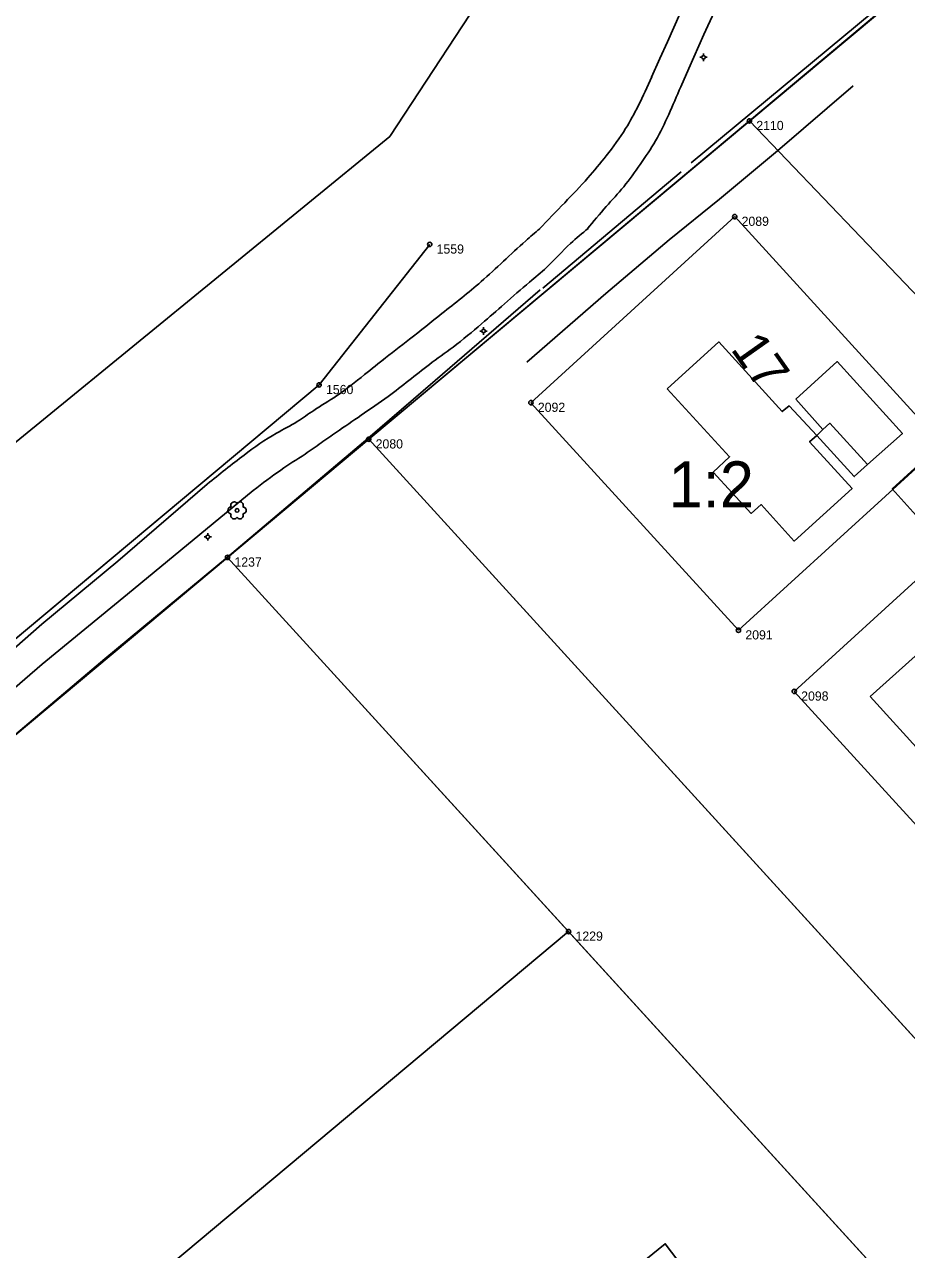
# Model space of a CAD drawing. Extents: x 1517478 to 1518189, y 6494860 to 6495389.
# Drawn here: x 1517883.6 to 1517979.5, y 6495107.4 to 6495240.6 of the extents above; entities that cross this region are included whole.
import ezdxf

# ---------------------------------------------------------------- set-up
doc = ezdxf.new("R2010")
doc.units = 0
for name, color, linetype in [('adress', 7, 'Continuous'), ('bostadshus', 7, 'Continuous'), ('fastighetsbeteckning', 7, 'Continuous'), ('gc_vag', 7, 'Continuous'), ('grans', 7, 'Continuous'), ('granspunkt', 7, 'Continuous'), ('granspunkt_text', 7, 'Continuous'), ('hack', 7, 'Continuous'), ('kvartersgrans', 7, 'Continuous'), ('kvartersgrans_utan_fastgr', 7, 'Continuous'), ('kvartersytor', 7, 'Continuous'), ('ledningar', 7, 'Continuous'), ('lovtrad', 7, 'Continuous'), ('parkeringskant', 7, 'Continuous'), ('skarmtak', 7, 'Continuous'), ('staket', 7, 'Continuous'), ('stolpe_belysning', 7, 'Continuous'), ('uthus', 7, 'Continuous')]:
    doc.layers.add(name, color=color, linetype=linetype)

msp = doc.modelspace()

# ---------------------------------------------------------------- linework, layer by layer
at = {"layer": 'bostadshus'}
for points in [[(1517953.5, 6495201.02), (1517959.1, 6495206.11), (1517966.02, 6495198.53), (1517966.76, 6495199.15), (1517969.76, 6495195.93), (1517968.99, 6495195.25), (1517973.6, 6495190.18), (1517967.31, 6495184.46), (1517963.71, 6495188.43), (1517962.62, 6495187.46), (1517958.49, 6495191.93), (1517960.28, 6495193.62), (1517953.5, 6495201.02)], [(1517975.57, 6495167.55), (1517980.48, 6495171.93), (1517981.83, 6495170.45), (1517987.06, 6495175.28), (1517988.1, 6495174.14), (1517992.61, 6495178.29), (1517991.59, 6495179.38), (1517991.82, 6495179.58), (1517997.11, 6495173.74), (1517992.09, 6495169.26), (1517991.75, 6495169.62), (1517988.32, 6495166.48), (1517991.2, 6495163.3), (1517987.55, 6495160.07), (1517984.13, 6495163.84), (1517981.3, 6495161.27), (1517975.57, 6495167.55)]]:
    msp.add_lwpolyline(points, dxfattribs=at)
at = {"layer": 'gc_vag'}
for points in [[(1517960.6, 6495254.37), (1517959.63, 6495252.05), (1517958.37, 6495249.52), (1517956.69, 6495245.83), (1517954.9, 6495241.83), (1517953.53, 6495238.72), (1517952.69, 6495236.93), (1517951.8, 6495234.88)], [(1517966.27, 6495254.47), (1517962.16, 6495249.73), (1517959.53, 6495243.94), (1517957.48, 6495239.51), (1517955.85, 6495235.83), (1517954.98, 6495233.83)], [(1517988.68, 6495187.89), (1517988.86, 6495187.55), (1517984.15, 6495183.26), (1517977.97, 6495190.13), (1517982.05, 6495193.87)], [(1517877.91, 6495168.79), (1517885.48, 6495175.44), (1517893.74, 6495182.28), (1517903.48, 6495190.65)], [(1517877.95, 6495164.55), (1517885.53, 6495171.07), (1517894.79, 6495178.7), (1517908.48, 6495189.97)]]:
    msp.add_lwpolyline(points, dxfattribs=at)
for points in [[(1517939.59, 6495218.37), (1517942.35, 6495221.24), (1517944.87, 6495223.93), (1517946.87, 6495226.35), (1517948.98, 6495229.3), (1517950.35, 6495231.77), (1517951.82, 6495234.93)], [(1517944.8, 6495218.37), (1517946.87, 6495220.82), (1517948.77, 6495222.98), (1517950.56, 6495225.4), (1517952.24, 6495227.98), (1517953.66, 6495230.83), (1517954.98, 6495233.83)], [(1517908.48, 6495189.97), (1517911.48, 6495192.18), (1517914.11, 6495193.92), (1517915.85, 6495195.13), (1517917.53, 6495196.29), (1517920.21, 6495198.13), (1517923.16, 6495200.18), (1517927.63, 6495203.66), (1517930.21, 6495205.55), (1517933.32, 6495208.08), (1517935.79, 6495210.24), (1517938.53, 6495212.61), (1517940.37, 6495214.19), (1517943, 6495216.82), (1517944.9, 6495218.45)], [(1517922.49, 6495204.07), (1517925.48, 6495206.4), (1517929, 6495209.19), (1517933.26, 6495212.66), (1517938.11, 6495217.09), (1517939.63, 6495218.4)], [(1517903.48, 6495190.65), (1517907.48, 6495193.81), (1517911, 6495196.18), (1517913.27, 6495197.45), (1517915.06, 6495198.66), (1517917.53, 6495200.24), (1517920.58, 6495202.55), (1517922.9, 6495204.4)]]:
    msp.add_spline(points, degree=3, dxfattribs=at)
at = {"layer": 'grans'}
for p, q in [((1517976.27, 6495241.68), (1517962.44, 6495230.13)), ((1517962.44, 6495230.13), (1517921.04, 6495195.52)), ((1517962.44, 6495230.13), (1517990.19, 6495201.16)), ((1517938.68, 6495199.5), (1517960.84, 6495219.72)), ((1517960.84, 6495219.72), (1517983.41, 6495194.98)), ((1517915.64, 6495201.43), (1517927.67, 6495216.7)), ((1517827.1, 6495127.44), (1517915.64, 6495201.43)), ((1517961.25, 6495174.76), (1517938.68, 6495199.5)), ((1517921.04, 6495195.52), (1517905.68, 6495182.68)), ((1517983.41, 6495194.98), (1517961.25, 6495174.76)), ((1517967.32, 6495168.11), (1517989.48, 6495188.33)), ((1517905.68, 6495182.68), (1517832.22, 6495121.28)), ((1517905.68, 6495182.68), (1517942.78, 6495142.01)), ((1517992.59, 6495140.41), (1517967.32, 6495168.11)), ((1517942.78, 6495142.01), (1517887.66, 6495095.94)), ((1517942.78, 6495142.01), (1518054.69, 6495019.3))]:
    msp.add_line(p, q, dxfattribs=at)
at = {"layer": 'granspunkt'}
for centre in [(1517962.44, 6495230.13), (1517960.84, 6495219.72), (1517927.67, 6495216.7), (1517915.64, 6495201.43), (1517938.68, 6495199.5), (1517921.04, 6495195.52), (1517905.68, 6495182.68), (1517961.25, 6495174.76), (1517967.32, 6495168.11), (1517942.78, 6495142.01)]:
    msp.add_circle(centre, 0.237, dxfattribs=at)
at = {"layer": 'hack'}
msp.add_line((1517928.27, 6495201.92), (1517939.69, 6495211.77), dxfattribs=at)
for points in [[(1517973.71, 6495233.93), (1517965.5, 6495226.88), (1517959.19, 6495221.61), (1517953.72, 6495217.19), (1517946.82, 6495211.35), (1517938.22, 6495203.92)], [(1517905.67, 6495182.7), (1517920.95, 6495195.6), (1517928.27, 6495201.92)], [(1517879.54, 6495160.85), (1517892.35, 6495171.65), (1517905.67, 6495182.7)]]:
    msp.add_lwpolyline(points, dxfattribs=at)
at = {"layer": 'kvartersgrans'}
for p, q in [((1517962.44, 6495230.13), (1517921.04, 6495195.52)), ((1517915.64, 6495201.43), (1517927.67, 6495216.7))]:
    msp.add_line(p, q, dxfattribs=at)
for points in [[(1517962.44, 6495230.13), (1517976.27, 6495241.68), (1517987.04, 6495250.68)], [(1517915.64, 6495201.43), (1517827.1, 6495127.44), (1517815.51, 6495117.75), (1517760.41, 6495089.02)], [(1517905.68, 6495182.68), (1517832.22, 6495121.28), (1517819.97, 6495111.05)], [(1517905.68, 6495182.68), (1517942.78, 6495142.01), (1518054.69, 6495019.3)]]:
    msp.add_lwpolyline(points, dxfattribs=at)
at = {"layer": 'kvartersgrans_utan_fastgr'}
msp.add_line((1517921.04, 6495195.52), (1518074.11, 6495027.69), dxfattribs=at)
at = {"layer": 'kvartersytor'}
for points in [[(1518074.11, 6495027.69), (1517921.04, 6495195.52), (1517981.66, 6495246.18), (1517987.04, 6495250.68), (1517987.4, 6495250.96), (1517987.81, 6495251.2), (1517988.26, 6495251.41), (1517988.58, 6495251.53), (1517989.03, 6495251.64), (1517989.55, 6495251.72), (1517989.95, 6495251.73), (1517990.42, 6495251.71), (1517990.85, 6495251.63), (1517991.35, 6495251.5), (1517991.85, 6495251.31), (1517992.28, 6495251.07), (1517992.57, 6495250.87), (1517992.84, 6495250.66), (1518007.2, 6495238.09), (1518015.81, 6495229.08), (1518018.08, 6495226.6), (1518024.14, 6495219.95), (1518073.64, 6495165.68), (1518099.97, 6495136.82)], [(1517717, 6495057.37), (1517819.97, 6495111.05), (1517905.68, 6495182.68), (1518054.69, 6495019.3)]]:
    msp.add_lwpolyline(points, dxfattribs=at)
at = {"layer": 'ledningar'}
msp.add_lwpolyline([(1517680.89, 6495088.62), (1517783.53, 6495114.28), (1517923.32, 6495228.43), (1517982.59, 6495318.69)], dxfattribs=at)
at = {"layer": 'lovtrad'}
msp.add_circle((1517906.72, 6495187.79), 0.2, dxfattribs=at)
for centre, start, end in [((1517906.4, 6495188.35), 29.1347, 212.3057), ((1517907.03, 6495188.35), 329.1331, 150.8613), ((1517906.08, 6495187.79), 89.5389, 268.9887), ((1517906.4, 6495187.24), 150.5831, 330.865), ((1517907.03, 6495187.24), 209.1844, 30.8583), ((1517907.35, 6495187.79), 269.1508, 90.8733)]:
    msp.add_arc(centre, 0.366, start, end, dxfattribs=at)
at = {"layer": 'parkeringskant'}
msp.add_lwpolyline([(1517964.72, 6495092.99), (1517953.28, 6495108.07), (1517928.01, 6495087.61), (1517943.33, 6495066.36)], dxfattribs=at)
at = {"layer": 'skarmtak'}
msp.add_line((1517970.41, 6495196.58), (1517969.76, 6495195.93), dxfattribs=at)
msp.add_lwpolyline([(1517969.76, 6495195.93), (1517973.84, 6495191.47), (1517975.27, 6495192.79)], dxfattribs=at)
at = {"layer": 'staket'}
msp.add_line((1517939.98, 6495211.93), (1517955.03, 6495224.61), dxfattribs=at)
msp.add_lwpolyline([(1517956.11, 6495225.56), (1517975.9, 6495241.99), (1517972.74, 6495244.41)], dxfattribs=at)
at = {"layer": 'stolpe_belysning'}
for p, q in [((1517957.25, 6495237.04), (1517957.05, 6495237.04)), ((1517957.45, 6495237.24), (1517957.45, 6495237.44)), ((1517957.45, 6495236.84), (1517957.45, 6495236.64)), ((1517957.65, 6495237.04), (1517957.85, 6495237.04)), ((1517933.33, 6495207.29), (1517933.13, 6495207.29)), ((1517933.53, 6495207.49), (1517933.53, 6495207.69)), ((1517933.73, 6495207.29), (1517933.93, 6495207.29)), ((1517933.53, 6495207.09), (1517933.53, 6495206.89)), ((1517903.33, 6495184.91), (1517903.13, 6495184.91)), ((1517903.53, 6495185.11), (1517903.53, 6495185.31)), ((1517903.53, 6495184.71), (1517903.53, 6495184.51)), ((1517903.73, 6495184.91), (1517903.93, 6495184.91))]:
    msp.add_line(p, q, dxfattribs=at)
for centre in [(1517957.45, 6495237.04), (1517933.53, 6495207.29), (1517903.53, 6495184.91)]:
    msp.add_circle(centre, 0.2, dxfattribs=at)
at = {"layer": 'uthus'}
msp.add_lwpolyline([(1517967.5, 6495199.87), (1517971.99, 6495203.96), (1517979.09, 6495196.15), (1517975.27, 6495192.79), (1517971.2, 6495197.27), (1517970.41, 6495196.58), (1517967.5, 6495199.87)], dxfattribs=at)

# ---------------------------------------------------------------- texts
at = {"layer": 'adress'}
msp.add_text('17', height=4, rotation=305.1968, dxfattribs=at).set_placement((1517960.32, 6495205.33))
at = {"layer": 'fastighetsbeteckning'}
msp.add_text('1:2', height=5, rotation=0.0021, dxfattribs=at).set_placement((1517953.64, 6495188.12))
at = {"layer": 'granspunkt_text'}
for s, p in [('2110', (1517963.19, 6495229.13)), ('2089', (1517961.59, 6495218.72)), ('1559', (1517928.42, 6495215.7)), ('1560', (1517916.39, 6495200.43)), ('2092', (1517939.43, 6495198.5)), ('2080', (1517921.79, 6495194.52)), ('1237', (1517906.43, 6495181.68)), ('2091', (1517962, 6495173.76)), ('2098', (1517968.07, 6495167.11)), ('1229', (1517943.53, 6495141.01))]:
    msp.add_text(s, height=1, dxfattribs=at).set_placement(p)

doc.saveas('drawing.dxf')
